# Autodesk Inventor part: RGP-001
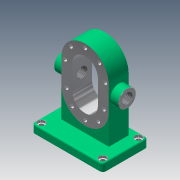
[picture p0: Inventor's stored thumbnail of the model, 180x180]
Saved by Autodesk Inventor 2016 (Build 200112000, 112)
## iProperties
Created: 2013-09
Part Number: RGP-001
Material: Aluminum 6061
Document SubType Name: Modeling
Designer: normanpa
Density: 2.71 g/cm^3
Appearance: 0 169 102
Mass: 3006.03 g
Surface Area: 1429.39 cm^2
Volume: 1109.24 cm^3
Description: PUMP BASE
Author: Autodesk
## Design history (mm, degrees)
sketch "Sketch1"
  geometry: L1 (-90, -57.5)-(90, -57.5); L2 (90, -57.5)-(90, 57.5); L3 (90, 57.5)-(-90, 57.5); L4 (-90, 57.5)-(-90, -57.5); L5 (-90, -57.5)-(90, 57.5); L6 (90, -57.5)-(-90, 57.5); 1 further point
  constraints: 12 end point, 2 midpoint, 2 parallel, 1 horizontal, 1 perpendicular
  dimensions: "d0" = 180 distance of L3.end L2.end; "d1" = 115 distance of L2.end L1.end
extrude "Extrusion1" new body sketch "Sketch1" distance "d2" = 20; taper "d3" = 0 deg
sketch "Sketch2"
  geometry: L1 (-90, -57.5)-(90, -57.5) reference; L2 (-90, 57.5)-(-90, -57.5) reference; 2 further points
  dimensions: "d4" = 12.5 distance from line of point (-77.5, -45) L1; "d5" = 12.5 distance from line of point (-77.5, -45) L2 (= d4)
hole "Hole1" sketch "Sketch2" at (-77.5, -45) diameter "d6" = 12; stored, may be unused: countersink angle "d10" = 90 deg, drill point angle "d12" = 118 deg; dims "d7" = 6, "d8" = 18, "d9" = 6, "d11" = 8
pattern_linear "Rectangular Pattern1" dims "d15" = 155
workplane "Work Plane1"
sketch "Sketch3"
  geometry: L1 (180, 20)-(0, 20) reference; L2 (30, 20)-(30, 156); L3 (150, 156)-(150, 20); A1 r 60 centre (90, 156) between (150, 156) and (30, 156); 2 further points
  constraints: 4 end point, 2 perpendicular, 2 point on circle, 2 point on line, 2 tangent, 1 centre point, 1 midpoint, 1 vertical alignment
  dimensions: "d20" = 136 distance of L2.start L2.end; "d21" = 60 radius of A1
extrude "Extrusion2" join sketch "Sketch3" stored distance "d22" = 50; taper "d23" = 0 deg
sketch "Sketch5"
  geometry: L1 (8, 124)-(172, 124); L2 (172, 124)-(172, 146); L3 (172, 146)-(8, 146); L4 (8, 146)-(8, 124); L5 (30, 20)-(30, 156) reference; L6 (30, 20)-(150, 20) reference; 2 further points
  constraints: 8 end point, 2 parallel, 1 horizontal, 1 midpoint, 1 perpendicular, 1 vertical alignment
  dimensions: "d24" = 22 distance between parallel lines of L4 L5; "d25" = 22 distance of L3.end L1.start; "d26" = 104 distance between parallel lines of L1 L6
revolve "Revolution1" sketch "Sketch5" stored, may be unused: angle "d27" = 90 deg
sketch "Sketch6"
  geometry: L1 (150, 20)-(150, 156) reference; L2 (90, 156)-(90, 96); L3 (122.5, 156)-(122.5, 96); L4 (57.5, 96)-(57.5, 156); A1 r 60 centre (90, 156) between (150, 156) and (30, 156) reference; A2 r 32.5 centre (90, 156) between (122.5, 156) and (57.5, 156); A3 r 32.5 centre (90, 96) between (57.5, 96) and (122.5, 96); 2 further points
  constraints: 8 end point, 4 point on circle, 4 tangent, 2 centre point, 2 parallel, 1 midpoint
  dimensions: "d28" = 60 distance of L2.start L2.end; "d29" = 32.5 radius of A3
extrude "Extrusion3" cut sketch "Sketch6" stored distance "d30" = 10; taper "d31" = 0 deg
sketch "Sketch7"
  geometry: L1 (30, 156)-(30, 20) reference; L2 (86.279, 156)-(39.279, 156); L3 (90, 96)-(43, 96); A1 r 32.5 centre (90, 156) between (122.5, 156) and (57.5, 156) reference; A2 r 32.5 centre (90, 96) between (57.5, 96) and (122.5, 96) reference; 11 further points
  constraints: 4 end point, 2 coincident, 1 parallel, 1 perpendicular, 10 other
  dimensions: "d32" = 47 distance of L2.start L2.end; "d33" = 47 distance of L3.start L3.end (= d32); "d36" = 180 deg dimension on A1.centre point (140.721, 156) point (39.279, 156); "d40" = 180 deg dimension on L3.start point (43, 96) point (137, 96)
hole "Hole2" sketch "Sketch7" at (39.279, 156), (43, 96), (54.135, 191.865), (90, 206.721), (125.865, 191.865), (140.721, 156), (56.766, 62.766), (90, 49), (123.234, 62.766), (137, 96) diameter "d42" = 10; stored, may be unused: countersink angle "d46" = 90 deg, drill point angle "d48" = 118 deg; dims "d43" = 6, "d44" = 4, "d45" = 2, "d47" = 8
hole "Hole3" diameter "d51" = 26.211; stored, may be unused: countersink angle "d55" = 90 deg, drill point angle "d57" = 118 deg; dims "d49" = 10, "d50" = 10, "d52" = 60, "d53" = 4, "d54" = 2, "d56" = 75.2
hole "Hole4" diameter "d60" = 26.211; stored, may be unused: countersink angle "d64" = 90 deg, drill point angle "d66" = 118 deg; dims "d58" = 10, "d59" = 10, "d61" = 60, "d62" = 4, "d63" = 2, "d65" = 75.2
fillet "Fillet1" dims "d67" = 4, "d68" = 8
fillet "Fillet2" dims "d69" = 2
chamfer "Chamfer1" distance "d70" = 1; stored, may be unused: second distance "d71" = 2, angle "d72" = 45 deg
chamfer "Chamfer2" distance "d73" = 0.5; stored, may be unused: second distance "d74" = 2, angle "d75" = 45 deg
sketch "Sketch8"
  geometry: L1 (57.5, -156)-(57.5, -96) reference; L2 (122.5, -96)-(122.5, -156) reference; L3 (30, -20)-(150, -20) reference; L4 (30, -20)-(30, -156) reference; L5 (150, -156)-(150, -20) reference; L6 (30, -96)-(30, -156); L7 (150, -156)-(150, -96); A1 r 32.5 centre (90, -156) between (57.5, -156) and (122.5, -156) reference; A2 r 32.5 centre (90, -96) between (122.5, -96) and (57.5, -96) reference; A3 r 60 centre (90, -156) between (30, -156) and (150, -156) reference; A4 r 60 centre (90, -156) between (30, -156) and (150, -156); A5 r 60 centre (90, -96) between (150, -96) and (30, -96); 1 further point
  constraints: 4 end point, 4 point on circle, 2 centre point, 3 other
extrude "Extrusion4" cut sketch "Sketch8" distance "d76" = 0.2; taper "d77" = 0 deg
workplane "Work Plane2"
mirror "Mirror1"
body "Solid1"
other parameters: "d19" = -45
